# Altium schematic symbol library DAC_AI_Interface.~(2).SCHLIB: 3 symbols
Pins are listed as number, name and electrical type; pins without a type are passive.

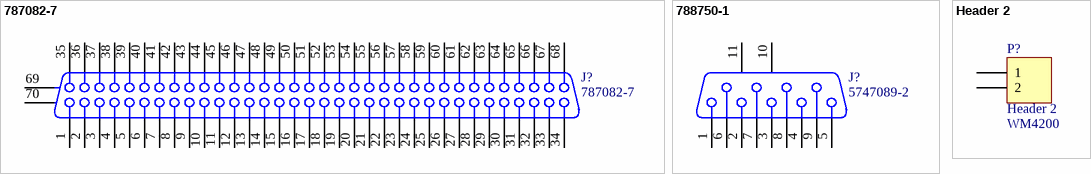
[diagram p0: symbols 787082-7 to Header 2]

## 787082-7
designator J?
Receptacle Assembly, Shielded, Right Angle, AMPLIMITE; Manufacturer: TE Connectivity; Description: CONN D-TYPE RCPT 68POS R/A SLDR; Plating: Bright,Copper; Voltage Rating: 30V; Current Rating: 1A; Gender: Female; Number of Positions: 68; Connector Type: Receptacle,Connector; Number of Ports: 1; Mating Alignment: No (Without); Mating Connector Lock: Yes (With); PCB Mount Retention: With; Pitch: 0.05inch; PCB Thickness: 1.57mm; Contact Post Length: 0.1inch; Hole Diameter: 0.109inch; Approvals: UL
footprint 787082-7 (Connector; D Subminiature 050 Series; 68 Position; Right Angle)
signal-integrity model D Subminiature
pins: 1, 2, 3, 4, 5, 6, 7, 8, 9, 10, 11, 12, 13, 14, 15, 16, 17, 18, 19, 20, 21, 22, 23, 24, 25, 26, 27, 28, 29, 30, 31, 32, 33, 34, 35, 36, 37, 38, 39, 40, 41, 42, 43, 44, 45, 46, 47, 48, 49, 50, 51, 52, 53, 54, 55, 56, 57, 58, 59, 60, 61, 62, 63, 64, 65, 66, 67, 68, 69 MH1, 70 MH2

## 788750-1
designator J?, comment 5747089-2
Receptacle Assembly, 9 Position, Right Angle, 8.08mm Series, Amplimite; Positions: 9; MatingConnector: 4-40 Threaded Insert; PCB_Layout: Complies with manufacturer's recommendation.; DrillSize: Corresponds to nominal value.
footprint 788750-1 (Connector; D Subminiature AMPLIMITE 2000; 9 Position; Right Angle)
signal-integrity model D Subminiature
footprint DB9/F
pins: 1, 2, 3, 4, 5, 6, 7, 8, 9, 10 MH1, 11 MH2

## Header 2
designator P?  Part Number: WM4200
Header, 2-Pin
footprint HDR1X2 (Connector; Header; 2 Position)
signal-integrity model Connector
pins: 1, 2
